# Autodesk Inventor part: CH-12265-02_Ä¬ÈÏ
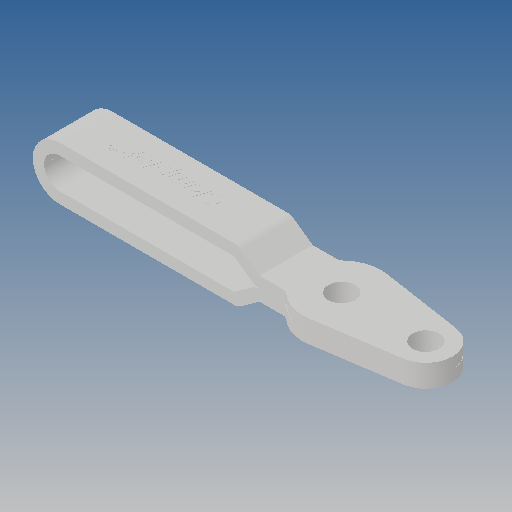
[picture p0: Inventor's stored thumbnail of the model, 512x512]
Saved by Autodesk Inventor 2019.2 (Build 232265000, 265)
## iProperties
Created: 2010-06
Part Number: CH-12265-02_Ä¬ÈÏ
Material: Ogólny
Document SubType Name: Modeling
Designer: CADENGINEERING4
Density: 1 g/cm^3
Appearance: Domyślna
Author: CADENGINEERING4
Revision Number: ÈÎºÎ
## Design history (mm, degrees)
feature "NONE"
feature "NONE:1"
node "Bryła1"
node "Bryła2"
